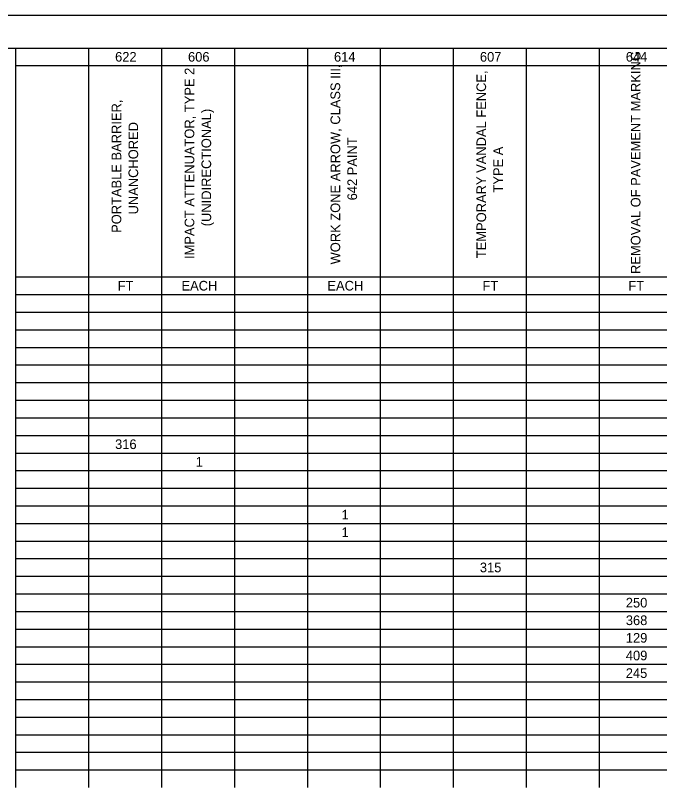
# Model space of a CAD drawing. Extents: x 0 to 34, y 0 to 22.
# Drawn here: x 14.09 to 23.97, y 10.15 to 22 of the extents above; entities that cross this region are included whole.
import ezdxf

# ---------------------------------------------------------------- set-up
doc = ezdxf.new("R2010")
doc.units = 0
for name, color, linetype in [('Default', 7, 'Continuous'), ('SH_Border', 7, 'Continuous'), ('SH_Cut_Line', 7, 'Continuous')]:
    doc.layers.add(name, color=color, linetype=linetype)

msp = doc.modelspace()

# ---------------------------------------------------------------- linework, layer by layer
at = {"layer": 'Default'}
for p, q in [((14.086, 21.5), (15.206, 21.5)), ((14.086, 21.5), (14.086, 21.23)), ((15.206, 21.5), (16.325, 21.5)), ((15.206, 21.5), (15.206, 21.23)), ((16.325, 21.5), (24.163, 21.5)), ((16.325, 21.5), (16.325, 21.23)), ((17.445, 21.5), (17.445, 21.23)), ((18.565, 21.5), (18.565, 21.23)), ((19.684, 21.5), (19.684, 21.23)), ((20.804, 21.5), (20.804, 21.23)), ((21.923, 21.5), (21.923, 21.23)), ((23.043, 21.5), (23.043, 21.23)), ((14.086, 21.23), (15.206, 21.23)), ((14.086, 21.23), (14.086, 20.959)), ((15.206, 21.23), (16.325, 21.23)), ((15.206, 21.23), (15.206, 20.959)), ((16.325, 21.23), (24.163, 21.23)), ((16.325, 21.23), (16.325, 20.959)), ((17.445, 21.23), (17.445, 20.959)), ((18.565, 21.23), (18.565, 20.959)), ((19.684, 21.23), (19.684, 20.959)), ((20.804, 21.23), (20.804, 20.959)), ((21.923, 21.23), (21.923, 20.959)), ((23.043, 21.23), (23.043, 20.959)), ((14.086, 20.959), (14.086, 20.689)), ((15.206, 20.959), (15.206, 20.689)), ((16.325, 20.959), (16.325, 20.689)), ((17.445, 20.959), (17.445, 20.689)), ((18.565, 20.959), (18.565, 20.689)), ((19.684, 20.959), (19.684, 20.689)), ((20.804, 20.959), (20.804, 20.689)), ((21.923, 20.959), (21.923, 20.689)), ((23.043, 20.959), (23.043, 20.689)), ((14.086, 20.689), (14.086, 20.419)), ((15.206, 20.689), (15.206, 20.419)), ((16.325, 20.689), (16.325, 20.419)), ((17.445, 20.689), (17.445, 20.419)), ((18.565, 20.689), (18.565, 20.419)), ((19.684, 20.689), (19.684, 20.419)), ((20.804, 20.689), (20.804, 20.419)), ((21.923, 20.689), (21.923, 20.419)), ((23.043, 20.689), (23.043, 20.419)), ((14.086, 20.419), (14.086, 20.149)), ((15.206, 20.419), (15.206, 20.149)), ((16.325, 20.419), (16.325, 20.149)), ((17.445, 20.419), (17.445, 20.149)), ((18.565, 20.419), (18.565, 20.149)), ((19.684, 20.419), (19.684, 20.149)), ((20.804, 20.419), (20.804, 20.149)), ((21.923, 20.419), (21.923, 20.149)), ((23.043, 20.419), (23.043, 20.149)), ((14.086, 20.149), (14.086, 19.878)), ((15.206, 20.149), (15.206, 19.878)), ((16.325, 20.149), (16.325, 19.878)), ((17.445, 20.149), (17.445, 19.878)), ((18.565, 20.149), (18.565, 19.878)), ((19.684, 20.149), (19.684, 19.878)), ((20.804, 20.149), (20.804, 19.878)), ((21.923, 20.149), (21.923, 19.878)), ((23.043, 20.149), (23.043, 19.878)), ((14.086, 19.878), (14.086, 19.608)), ((15.206, 19.878), (15.206, 19.608)), ((16.325, 19.878), (16.325, 19.608)), ((17.445, 19.878), (17.445, 19.608)), ((18.565, 19.878), (18.565, 19.608)), ((19.684, 19.878), (19.684, 19.608)), ((20.804, 19.878), (20.804, 19.608)), ((21.923, 19.878), (21.923, 19.608)), ((23.043, 19.878), (23.043, 19.608)), ((14.086, 19.608), (14.086, 19.068)), ((15.206, 19.608), (15.206, 19.068)), ((16.325, 19.608), (16.325, 19.068)), ((17.445, 19.608), (17.445, 19.068)), ((18.565, 19.608), (18.565, 19.068)), ((19.684, 19.608), (19.684, 19.068)), ((20.804, 19.608), (20.804, 19.068)), ((21.923, 19.608), (21.923, 19.068)), ((23.043, 19.608), (23.043, 19.068)), ((14.086, 19.068), (14.086, 18.257)), ((15.206, 19.068), (15.206, 18.257)), ((16.325, 19.068), (16.325, 18.257)), ((17.445, 19.068), (17.445, 18.257)), ((18.565, 19.068), (18.565, 18.257)), ((19.684, 19.068), (19.684, 18.257)), ((20.804, 19.068), (20.804, 18.257)), ((21.923, 19.068), (21.923, 18.257)), ((23.043, 19.068), (23.043, 18.257)), ((14.086, 18.257), (14.086, 17.987)), ((15.206, 18.257), (15.206, 17.987)), ((16.325, 18.257), (16.325, 17.987)), ((17.445, 18.257), (17.445, 17.987)), ((18.565, 18.257), (18.565, 17.987)), ((19.684, 18.257), (19.684, 17.987)), ((20.804, 18.257), (20.804, 17.987)), ((21.923, 18.257), (21.923, 17.987)), ((23.043, 18.257), (23.043, 17.987)), ((14.086, 17.987), (15.206, 17.987)), ((14.086, 17.987), (14.086, 17.446)), ((15.206, 17.987), (16.325, 17.987)), ((15.206, 17.987), (15.206, 17.446)), ((16.325, 17.987), (24.163, 17.987)), ((16.325, 17.987), (16.325, 17.446)), ((17.445, 17.987), (17.445, 17.446)), ((18.565, 17.987), (18.565, 17.446)), ((19.684, 17.987), (19.684, 17.446)), ((20.804, 17.987), (20.804, 17.446)), ((21.923, 17.987), (21.923, 17.446)), ((23.043, 17.987), (23.043, 17.446)), ((14.086, 17.716), (15.206, 17.716)), ((15.206, 17.716), (16.325, 17.716)), ((16.325, 17.716), (24.163, 17.716)), ((14.086, 17.446), (15.206, 17.446)), ((14.086, 17.446), (14.086, 17.176)), ((15.206, 17.446), (16.325, 17.446)), ((15.206, 17.446), (15.206, 17.176)), ((16.325, 17.446), (24.163, 17.446)), ((16.325, 17.446), (16.325, 17.176)), ((17.445, 17.446), (17.445, 17.176)), ((18.565, 17.446), (18.565, 17.176)), ((19.684, 17.446), (19.684, 17.176)), ((20.804, 17.446), (20.804, 17.176)), ((21.923, 17.446), (21.923, 17.176)), ((23.043, 17.446), (23.043, 17.176)), ((14.086, 17.176), (15.206, 17.176)), ((14.086, 17.176), (14.086, 16.095)), ((15.206, 17.176), (16.325, 17.176)), ((15.206, 17.176), (15.206, 16.095)), ((16.325, 17.176), (24.163, 17.176)), ((16.325, 17.176), (16.325, 16.095)), ((17.445, 17.176), (17.445, 16.095)), ((18.565, 17.176), (18.565, 16.095)), ((19.684, 17.176), (19.684, 16.095)), ((20.804, 17.176), (20.804, 16.095)), ((21.923, 17.176), (21.923, 16.095)), ((23.043, 17.176), (23.043, 16.095)), ((14.086, 16.906), (15.206, 16.906)), ((15.206, 16.906), (16.325, 16.906)), ((16.325, 16.906), (24.163, 16.906)), ((14.086, 16.635), (15.206, 16.635)), ((15.206, 16.635), (16.325, 16.635)), ((16.325, 16.635), (24.163, 16.635)), ((14.086, 16.365), (15.206, 16.365)), ((15.206, 16.365), (16.325, 16.365)), ((16.325, 16.365), (24.163, 16.365)), ((14.086, 16.095), (15.206, 16.095)), ((14.086, 16.095), (14.086, 15.825)), ((15.206, 16.095), (16.325, 16.095)), ((15.206, 16.095), (15.206, 15.825)), ((16.325, 16.095), (24.163, 16.095)), ((16.325, 16.095), (16.325, 15.825)), ((17.445, 16.095), (17.445, 15.825)), ((18.565, 16.095), (18.565, 15.825)), ((19.684, 16.095), (19.684, 15.825)), ((20.804, 16.095), (20.804, 15.825)), ((21.923, 16.095), (21.923, 15.825)), ((23.043, 16.095), (23.043, 15.825)), ((14.086, 15.825), (15.206, 15.825)), ((14.086, 15.825), (14.086, 15.284)), ((15.206, 15.825), (16.325, 15.825)), ((15.206, 15.825), (15.206, 15.284)), ((16.325, 15.825), (24.163, 15.825)), ((16.325, 15.825), (16.325, 15.284)), ((17.445, 15.825), (17.445, 15.284)), ((18.565, 15.825), (18.565, 15.284)), ((19.684, 15.825), (19.684, 15.284)), ((20.804, 15.825), (20.804, 15.284)), ((21.923, 15.825), (21.923, 15.284)), ((23.043, 15.825), (23.043, 15.284)), ((14.086, 15.554), (15.206, 15.554)), ((15.206, 15.554), (16.325, 15.554)), ((16.325, 15.554), (24.163, 15.554)), ((14.086, 15.284), (15.206, 15.284)), ((14.086, 15.284), (14.086, 14.744)), ((15.206, 15.284), (16.325, 15.284)), ((15.206, 15.284), (15.206, 14.744)), ((16.325, 15.284), (24.163, 15.284)), ((16.325, 15.284), (16.325, 14.744)), ((17.445, 15.284), (17.445, 14.744)), ((18.565, 15.284), (18.565, 14.744)), ((19.684, 15.284), (19.684, 14.744)), ((20.804, 15.284), (20.804, 14.744)), ((21.923, 15.284), (21.923, 14.744)), ((23.043, 15.284), (23.043, 14.744)), ((14.086, 15.014), (15.206, 15.014)), ((15.206, 15.014), (16.325, 15.014)), ((16.325, 15.014), (24.163, 15.014)), ((14.086, 14.744), (15.206, 14.744)), ((14.086, 14.744), (14.086, 14.473)), ((15.206, 14.744), (16.325, 14.744)), ((15.206, 14.744), (15.206, 14.473)), ((16.325, 14.744), (24.163, 14.744)), ((16.325, 14.744), (16.325, 14.473)), ((17.445, 14.744), (17.445, 14.473)), ((18.565, 14.744), (18.565, 14.473)), ((19.684, 14.744), (19.684, 14.473)), ((20.804, 14.744), (20.804, 14.473)), ((21.923, 14.744), (21.923, 14.473)), ((23.043, 14.744), (23.043, 14.473)), ((14.086, 14.473), (15.206, 14.473)), ((14.086, 14.473), (14.086, 13.933)), ((15.206, 14.473), (16.325, 14.473)), ((15.206, 14.473), (15.206, 13.933)), ((16.325, 14.473), (24.163, 14.473)), ((16.325, 14.473), (16.325, 13.933)), ((17.445, 14.473), (17.445, 13.933)), ((18.565, 14.473), (18.565, 13.933)), ((19.684, 14.473), (19.684, 13.933)), ((20.804, 14.473), (20.804, 13.933)), ((21.923, 14.473), (21.923, 13.933)), ((23.043, 14.473), (23.043, 13.933)), ((14.086, 14.203), (15.206, 14.203)), ((15.206, 14.203), (16.325, 14.203)), ((16.325, 14.203), (24.163, 14.203)), ((14.086, 13.933), (15.206, 13.933)), ((14.086, 13.933), (14.086, 13.663)), ((15.206, 13.933), (16.325, 13.933)), ((15.206, 13.933), (15.206, 13.663)), ((16.325, 13.933), (24.163, 13.933)), ((16.325, 13.933), (16.325, 13.663)), ((17.445, 13.933), (17.445, 13.663)), ((18.565, 13.933), (18.565, 13.663)), ((19.684, 13.933), (19.684, 13.663)), ((20.804, 13.933), (20.804, 13.663)), ((21.923, 13.933), (21.923, 13.663)), ((23.043, 13.933), (23.043, 13.663)), ((14.086, 13.663), (15.206, 13.663)), ((14.086, 13.663), (14.086, 12.852)), ((15.206, 13.663), (16.325, 13.663)), ((15.206, 13.663), (15.206, 12.852)), ((16.325, 13.663), (24.163, 13.663)), ((16.325, 13.663), (16.325, 12.852)), ((17.445, 13.663), (17.445, 12.852)), ((18.565, 13.663), (18.565, 12.852)), ((19.684, 13.663), (19.684, 12.852)), ((20.804, 13.663), (20.804, 12.852)), ((21.923, 13.663), (21.923, 12.852)), ((23.043, 13.663), (23.043, 12.852)), ((14.086, 13.392), (15.206, 13.392)), ((15.206, 13.392), (16.325, 13.392)), ((16.325, 13.392), (24.163, 13.392)), ((14.086, 13.122), (15.206, 13.122)), ((15.206, 13.122), (16.325, 13.122)), ((16.325, 13.122), (24.163, 13.122)), ((14.086, 12.852), (15.206, 12.852)), ((14.086, 12.852), (14.086, 12.311)), ((15.206, 12.852), (16.325, 12.852)), ((15.206, 12.852), (15.206, 12.311)), ((16.325, 12.852), (24.163, 12.852)), ((16.325, 12.852), (16.325, 12.311)), ((17.445, 12.852), (17.445, 12.311)), ((18.565, 12.852), (18.565, 12.311)), ((19.684, 12.852), (19.684, 12.311)), ((20.804, 12.852), (20.804, 12.311)), ((21.923, 12.852), (21.923, 12.311)), ((23.043, 12.852), (23.043, 12.311)), ((14.086, 12.582), (15.206, 12.582)), ((15.206, 12.582), (16.325, 12.582)), ((16.325, 12.582), (24.163, 12.582)), ((14.086, 12.311), (15.206, 12.311)), ((14.086, 12.311), (14.086, 11.501)), ((15.206, 12.311), (16.325, 12.311)), ((15.206, 12.311), (15.206, 11.501)), ((16.325, 12.311), (24.163, 12.311)), ((16.325, 12.311), (16.325, 11.501)), ((17.445, 12.311), (17.445, 11.501)), ((18.565, 12.311), (18.565, 11.501)), ((19.684, 12.311), (19.684, 11.501)), ((20.804, 12.311), (20.804, 11.501)), ((21.923, 12.311), (21.923, 11.501)), ((23.043, 12.311), (23.043, 11.501)), ((14.086, 12.041), (15.206, 12.041)), ((15.206, 12.041), (16.325, 12.041)), ((16.325, 12.041), (24.163, 12.041)), ((14.086, 11.771), (15.206, 11.771)), ((15.206, 11.771), (16.325, 11.771)), ((16.325, 11.771), (24.163, 11.771)), ((14.086, 11.501), (15.206, 11.501)), ((14.086, 11.501), (14.086, 10.96)), ((15.206, 11.501), (16.325, 11.501)), ((15.206, 11.501), (15.206, 10.96)), ((16.325, 11.501), (24.163, 11.501)), ((16.325, 11.501), (16.325, 10.96)), ((17.445, 11.501), (17.445, 10.96)), ((18.565, 11.501), (18.565, 10.96)), ((19.684, 11.501), (19.684, 10.96)), ((20.804, 11.501), (20.804, 10.96)), ((21.923, 11.501), (21.923, 10.96)), ((23.043, 11.501), (23.043, 10.96)), ((14.086, 11.23), (15.206, 11.23)), ((15.206, 11.23), (16.325, 11.23)), ((16.325, 11.23), (24.163, 11.23)), ((14.086, 10.96), (15.206, 10.96)), ((14.086, 10.96), (14.086, 10.149)), ((15.206, 10.96), (16.325, 10.96)), ((15.206, 10.96), (15.206, 10.149)), ((16.325, 10.96), (24.163, 10.96)), ((16.325, 10.96), (16.325, 10.149)), ((17.445, 10.96), (17.445, 10.149)), ((18.565, 10.96), (18.565, 10.149)), ((19.684, 10.96), (19.684, 10.149)), ((20.804, 10.96), (20.804, 10.149)), ((21.923, 10.96), (21.923, 10.149)), ((23.043, 10.96), (23.043, 10.149)), ((14.086, 10.69), (15.206, 10.69)), ((15.206, 10.69), (16.325, 10.69)), ((16.325, 10.69), (24.163, 10.69)), ((14.086, 10.42), (15.206, 10.42)), ((15.206, 10.42), (16.325, 10.42)), ((16.325, 10.42), (24.163, 10.42))]:
    msp.add_line(p, q, dxfattribs=at)
at = {"layer": 'SH_Border'}
msp.add_lwpolyline([(1.5, 21.5), (33.5, 21.5), (33.5, 0.5), (1.5, 0.5)], close=True, dxfattribs=at)
at = {"layer": 'SH_Cut_Line'}
msp.add_lwpolyline([(0, 0), (34, 0), (34, 22), (0, 22)], close=True, dxfattribs=at)

# ---------------------------------------------------------------- texts
at = {"layer": 'Default'}
for s, p in [('622', (15.615, 21.291)), ('606', (16.734, 21.291)), ('614', (18.974, 21.291)), ('607', (21.213, 21.291)), ('644', (23.452, 21.291)), ('FT', (15.654, 17.778)), ('EACH', (16.634, 17.778)), ('EACH', (18.873, 17.778)), ('FT', (21.252, 17.778)), ('FT', (23.491, 17.778)), ('316', (15.615, 15.345)), ('1', (16.851, 15.075)), ('1', (19.09, 14.264)), ('1', (19.09, 13.994)), ('315', (21.212, 13.454)), ('250', (23.452, 12.913)), ('368', (23.452, 12.643)), ('129', (23.452, 12.373)), ('409', (23.452, 12.102)), ('245', (23.451, 11.832))]:
    msp.add_text(s, height=0.148, dxfattribs=at).set_placement(p)
for s, p in [('REMOVAL OF PAVEMENT MARKING', (23.677, 18.032)), ('WORK ZONE ARROW, CLASS III, ', (19.069, 18.179)), ('IMPACT ATTENUATOR, TYPE 2 ', (16.83, 18.262)), ('TEMPORARY VANDAL FENCE, ', (21.308, 18.275)), ('PORTABLE BARRIER, ', (15.71, 18.663)), ('(UNIDIRECTIONAL)', (17.089, 18.764)), ('UNANCHORED', (15.969, 18.946)), ('642 PAINT', (19.328, 19.162)), ('TYPE A', (21.567, 19.282))]:
    msp.add_text(s, height=0.148, rotation=90, dxfattribs=at).set_placement(p)

doc.saveas('drawing.dxf')
